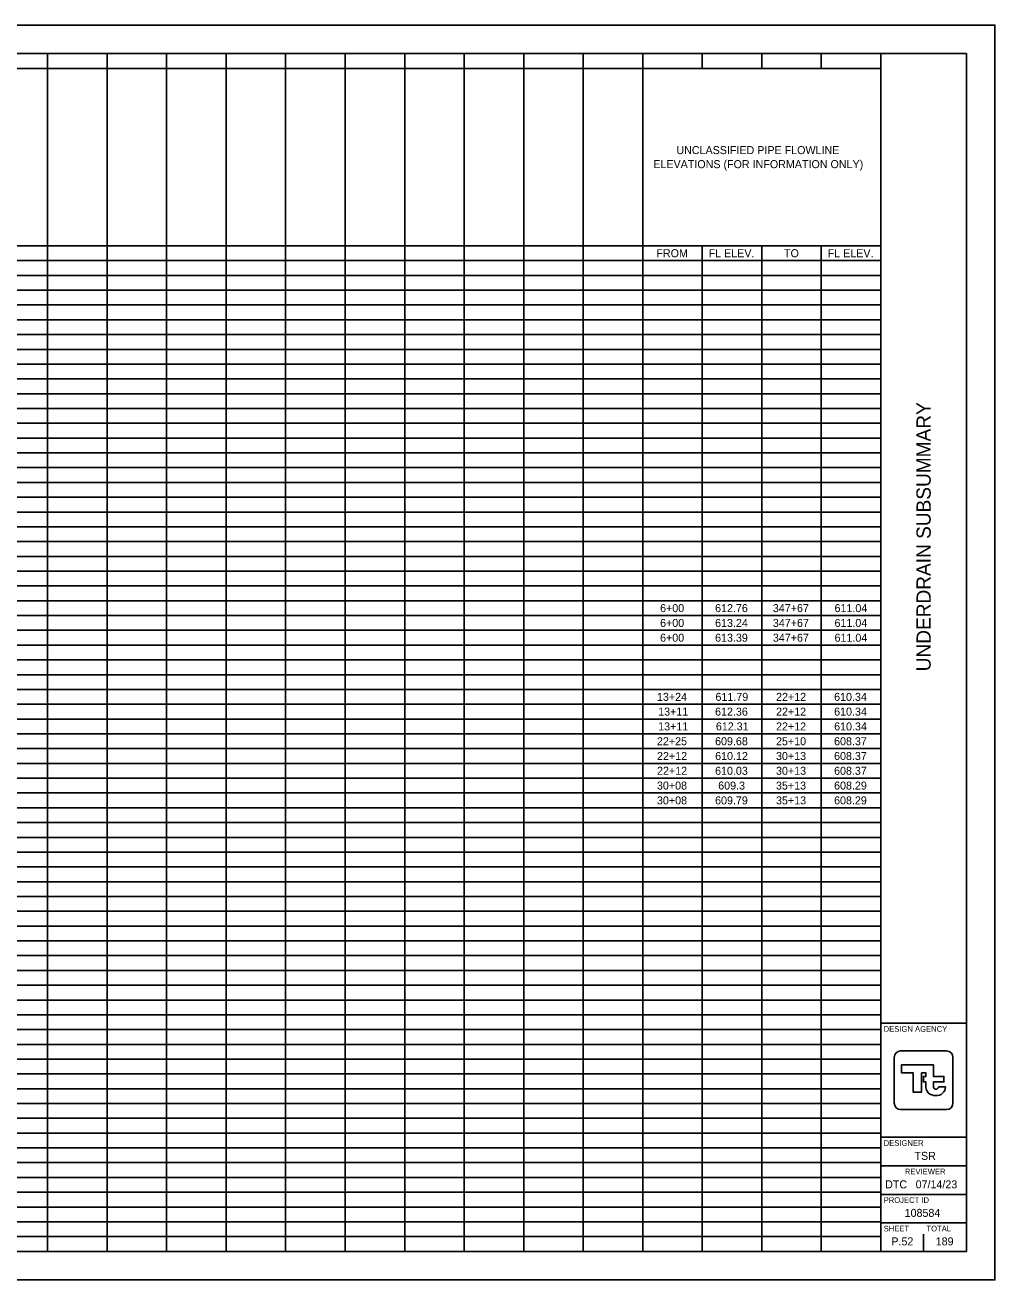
# Model space of a CAD drawing. Extents: x 0 to 34, y 0 to 22.
# Drawn here: x 17 to 34, y 0 to 22 of the extents above; entities that cross this region are included whole.
import ezdxf

# ---------------------------------------------------------------- set-up
doc = ezdxf.new("R2010")
doc.units = 0
for name, color, linetype in [('SH_Border', 7, 'Continuous'), ('SH_Cut_Line', 7, 'Continuous'), ('SH_Data', 7, 'Continuous'), ('SH_Text', 7, 'Continuous')]:
    doc.layers.add(name, color=color, linetype=linetype)

msp = doc.modelspace()

# ---------------------------------------------------------------- linework, layer by layer
at = {"layer": 'SH_Border'}
for p, q in [((32, 0.5), (32, 21.5)), ((32, 4.5), (33.5, 4.5)), ((32, 2.5), (33.5, 2.5)), ((32, 2), (33.5, 2)), ((32, 1.5), (33.5, 1.5)), ((32, 1), (33.5, 1))]:
    msp.add_line(p, q, dxfattribs=at)
msp.add_lwpolyline([(1.5, 21.5), (33.5, 21.5), (33.5, 0.5), (1.5, 0.5)], close=True, dxfattribs=at)
at = {"layer": 'SH_Cut_Line'}
msp.add_lwpolyline([(0, 0), (34, 0), (34, 22), (0, 22)], close=True, dxfattribs=at)
at = {"layer": 'SH_Data'}
for p, q in [((32.75, 3.5), (32.75, 3.5)), ((32.791, 3.415), (32.791, 3.415)), ((33.136, 3.385), (33.015, 3.385)), ((32.375, 0.675), (32.375, 0.675)), ((32.75, 0.5), (32.75, 0.8))]:
    msp.add_line(p, q, dxfattribs=at)
for points in [[(32.348, 4.014), (33.152, 4.014)], [(32.236, 3.099), (32.236, 3.901)], [(32.922, 3.399), (32.922, 3.47), (33.107, 3.47), (33.107, 3.568), (32.922, 3.568), (32.922, 3.768), (32.361, 3.768), (32.361, 3.632), (32.566, 3.632), (32.566, 3.294), (32.715, 3.294), (32.715, 3.63), (32.79, 3.63), (32.79, 3.568), (32.748, 3.568), (32.748, 3.47), (32.79, 3.47), (32.79, 3.415), (32.791, 3.415)], [(33.264, 3.901), (33.264, 3.099)], [(33.152, 2.986), (32.348, 2.986)]]:
    msp.add_lwpolyline(points, dxfattribs=at)
for centre, radius, start, end in [((32.348, 3.901), 0.113, 90, 180), ((33.152, 3.901), 0.113, 360, 90), ((32.949, 3.392), 0.16, 171.8856, 274.8323), ((32.968, 3.392), 0.0473, 171.8856, 350.9243), ((32.976, 3.392), 0.16, 265.1677, 357.3201), ((32.348, 3.099), 0.113, 180, 270), ((33.152, 3.099), 0.113, 270, 360)]:
    msp.add_arc(centre, radius, start, end, dxfattribs=at)
at = {"layer": 'SH_Text'}
for p, q in [((1.5, 21.5), (32, 21.5)), ((17.394, 21.5), (17.394, 0.5)), ((18.438, 21.5), (18.438, 0.5)), ((19.481, 21.5), (19.481, 0.5)), ((20.524, 21.5), (20.524, 0.5)), ((21.567, 21.5), (21.567, 0.5)), ((22.611, 21.5), (22.611, 0.5)), ((23.654, 21.5), (23.654, 0.5)), ((24.697, 21.5), (24.697, 0.5)), ((25.74, 21.5), (25.74, 0.5)), ((26.784, 21.5), (26.784, 0.5)), ((27.827, 21.5), (27.827, 0.5)), ((28.87, 21.5), (28.87, 21.241)), ((29.913, 21.5), (29.913, 21.241)), ((30.957, 21.5), (30.957, 21.241)), ((32, 21.5), (32, 0.5)), ((9.048, 21.241), (32, 21.241)), ((9.048, 18.13), (32, 18.13)), ((28.87, 18.13), (28.87, 0.5)), ((29.913, 18.13), (29.913, 0.5)), ((30.957, 18.13), (30.957, 0.5)), ((1.5, 17.87), (32, 17.87)), ((1.5, 17.611), (32, 17.611)), ((1.5, 17.352), (32, 17.352)), ((1.5, 17.093), (32, 17.093)), ((1.5, 16.833), (32, 16.833)), ((1.5, 16.574), (32, 16.574)), ((1.5, 16.315), (32, 16.315)), ((1.5, 16.056), (32, 16.056)), ((1.5, 15.796), (32, 15.796)), ((1.5, 15.537), (32, 15.537)), ((1.5, 15.278), (32, 15.278)), ((1.5, 15.019), (32, 15.019)), ((1.5, 14.759), (32, 14.759)), ((1.5, 14.5), (32, 14.5)), ((1.5, 14.241), (32, 14.241)), ((1.5, 13.981), (32, 13.981)), ((1.5, 13.722), (32, 13.722)), ((1.5, 13.463), (32, 13.463)), ((1.5, 13.204), (32, 13.204)), ((1.5, 12.944), (32, 12.944)), ((1.5, 12.685), (32, 12.685)), ((1.5, 12.426), (32, 12.426)), ((1.5, 12.167), (32, 12.167)), ((1.5, 11.907), (32, 11.907)), ((1.5, 11.648), (32, 11.648)), ((1.5, 11.389), (32, 11.389)), ((1.5, 11.13), (32, 11.13)), ((1.5, 10.87), (32, 10.87)), ((1.5, 10.611), (32, 10.611)), ((1.5, 10.352), (32, 10.352)), ((1.5, 10.093), (32, 10.093)), ((1.5, 9.833), (32, 9.833)), ((1.5, 9.574), (32, 9.574)), ((1.5, 9.315), (32, 9.315)), ((1.5, 9.056), (32, 9.056)), ((1.5, 8.796), (32, 8.796)), ((1.5, 8.537), (32, 8.537)), ((1.5, 8.278), (32, 8.278)), ((1.5, 8.019), (32, 8.019)), ((1.5, 7.759), (32, 7.759)), ((1.5, 7.5), (32, 7.5)), ((1.5, 7.241), (32, 7.241)), ((1.5, 6.981), (32, 6.981)), ((1.5, 6.722), (32, 6.722)), ((1.5, 6.463), (32, 6.463)), ((1.5, 6.204), (32, 6.204)), ((1.5, 5.944), (32, 5.944)), ((1.5, 5.685), (32, 5.685)), ((1.5, 5.426), (32, 5.426)), ((1.5, 5.167), (32, 5.167)), ((1.5, 4.907), (32, 4.907)), ((1.5, 4.648), (32, 4.648)), ((1.5, 4.389), (32, 4.389)), ((1.5, 4.13), (32, 4.13)), ((1.5, 3.87), (32, 3.87)), ((1.5, 3.611), (32, 3.611)), ((1.5, 3.352), (32, 3.352)), ((1.5, 3.093), (32, 3.093)), ((1.5, 2.833), (32, 2.833)), ((1.5, 2.574), (32, 2.574)), ((1.5, 2.315), (32, 2.315)), ((1.5, 2.056), (32, 2.056)), ((1.5, 1.796), (32, 1.796)), ((1.5, 1.537), (32, 1.537)), ((1.5, 1.278), (32, 1.278)), ((1.5, 1.019), (32, 1.019)), ((1.5, 0.759), (32, 0.759)), ((1.5, 0.5), (32, 0.5))]:
    msp.add_line(p, q, dxfattribs=at)

# ---------------------------------------------------------------- texts
at = {"layer": 'SH_Data'}
msp.add_text('UNDERDRAIN SUBSUMMARY', height=0.25, rotation=90, dxfattribs=at).set_placement((32.875, 10.67))
for s, height, p in [('DESIGN AGENCY', 0.1, (32.05, 4.35)), ('DESIGNER', 0.1, (32.05, 2.35)), ('TSR', 0.14, (32.59, 2.105)), ('REVIEWER', 0.1, (32.422, 1.85)), ('DTC', 0.14, (32.076, 1.605)), ('07/14/23', 0.14, (32.611, 1.605)), ('PROJECT ID', 0.1, (32.05, 1.35)), ('108584', 0.14, (32.418, 1.105)), ('SHEET', 0.1, (32.05, 0.85)), ('TOTAL', 0.1, (32.8, 0.85)), ('P.52', 0.14, (32.185, 0.605)), ('189', 0.14, (32.963, 0.605))]:
    msp.add_text(s, height=height, dxfattribs=at).set_placement(p)
at = {"layer": 'SH_Text'}
for s, height, p in [('UNCLASSIFIED PIPE FLOWLINE ', 0.14031, (28.417, 19.738)), ('ELEVATIONS (FOR INFORMATION ONLY)', 0.14031, (28.012, 19.492)), ('FROM', 0.1403, (28.066, 17.93)), ('FL ELEV.', 0.1403, (28.982, 17.93)), ('TO', 0.1403, (30.304, 17.93)), ('FL ELEV.', 0.1403, (31.069, 17.93)), ('6+00', 0.1403, (28.131, 11.708)), ('612.76', 0.1403, (29.095, 11.708)), ('347+67', 0.1403, (30.108, 11.708)), ('611.04', 0.1403, (31.189, 11.708)), ('6+00', 0.1403, (28.131, 11.448)), ('613.24', 0.1403, (29.095, 11.448)), ('347+67', 0.1403, (30.108, 11.448)), ('611.04', 0.1403, (31.189, 11.448)), ('6+00', 0.1403, (28.131, 11.189)), ('613.39', 0.1403, (29.095, 11.189)), ('347+67', 0.1403, (30.108, 11.189)), ('611.04', 0.1403, (31.189, 11.189)), ('13+24', 0.1403, (28.077, 10.152)), ('611.79', 0.1403, (29.102, 10.152)), ('22+12', 0.1403, (30.164, 10.152)), ('610.34', 0.1403, (31.182, 10.152)), ('13+11', 0.1403, (28.097, 9.893)), ('612.36', 0.1403, (29.095, 9.893)), ('22+12', 0.1403, (30.164, 9.893)), ('610.34', 0.1403, (31.182, 9.893)), ('13+11', 0.1403, (28.097, 9.634)), ('612.31', 0.1403, (29.109, 9.634)), ('22+12', 0.1403, (30.164, 9.634)), ('610.34', 0.1403, (31.182, 9.634)), ('22+25', 0.1403, (28.076, 9.374)), ('609.68', 0.1403, (29.095, 9.374)), ('25+10', 0.1403, (30.163, 9.374)), ('608.37', 0.1403, (31.181, 9.374)), ('22+12', 0.1403, (28.077, 9.115)), ('610.12', 0.1403, (29.096, 9.115)), ('30+13', 0.1403, (30.163, 9.115)), ('608.37', 0.1403, (31.181, 9.115)), ('22+12', 0.1403, (28.077, 8.856)), ('610.03', 0.1403, (29.095, 8.856)), ('30+13', 0.1403, (30.163, 8.856)), ('608.37', 0.1403, (31.181, 8.856)), ('30+08', 0.1403, (28.076, 8.597)), ('609.3', 0.1403, (29.15, 8.597)), ('35+13', 0.1403, (30.163, 8.597)), ('608.29', 0.1403, (31.181, 8.597)), ('30+08', 0.1403, (28.076, 8.337)), ('609.79', 0.1403, (29.095, 8.337)), ('35+13', 0.1403, (30.163, 8.337)), ('608.29', 0.1403, (31.181, 8.337))]:
    msp.add_text(s, height=height, dxfattribs=at).set_placement(p)

doc.saveas('drawing.dxf')
